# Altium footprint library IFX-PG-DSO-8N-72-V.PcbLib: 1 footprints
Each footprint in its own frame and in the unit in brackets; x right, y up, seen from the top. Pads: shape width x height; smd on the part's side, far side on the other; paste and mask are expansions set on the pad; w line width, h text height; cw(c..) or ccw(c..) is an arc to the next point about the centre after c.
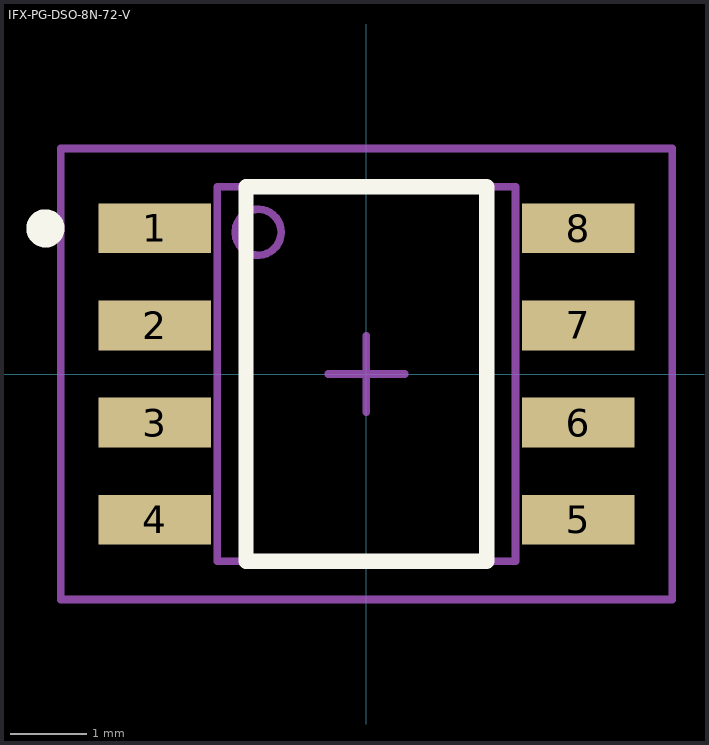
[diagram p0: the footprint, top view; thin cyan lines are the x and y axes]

## IFX-PG-DSO-8N-72-V [mm] "SOIC,1.27mm pitch;8 pin,3.90mm W X 4.90mm L X 1.75mm H body"
height 1.75
pads (8):
  rect 1.47x0.65 smd paste+0 mask+0: 1(-2.77,1.905) 2(-2.77,0.635) 3(-2.77,-0.635) 4(-2.77,-1.905) 5(2.77,-1.905) 6(2.77,-0.635) 7(2.77,0.635) 8(2.77,1.905)
Top Overlay:
  circle w0.25: c-4.2,1.905 r0.125
  lines w0.2: -1.575,-2.45 1.575,-2.45 1.575,2.45 -1.575,2.45 -1.575,-2.45
M3 (ASY_Text_Top):
  text ".DESIGNATOR" at -3.641,-0.384 h1.2
M13 (CMP_Body_OTL_Top):
  circle w0.1: c-1.415,1.855 r0.3
  lines w0.1: -1.95,-2.45 1.95,-2.45 1.95,2.45 -1.95,2.45 -1.95,-2.45
M15 (CMP_Courtyard_Top):
  lines w0.1: -0.5,0 0.5,0 ; 0,-0.5 0,0.5 ; -4,-2.95 4,-2.95 4,2.95 -4,2.95 -4,-2.95
3D body "DSO-8-16.stp": height 1.76, standoff 0, extent -3,-2.5 3,2.5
